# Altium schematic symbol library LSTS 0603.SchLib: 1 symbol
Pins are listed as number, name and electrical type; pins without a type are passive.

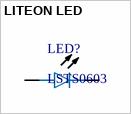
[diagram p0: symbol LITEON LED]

## LITEON LED
designator LED?, comment LSTS0603
LITE ON LED 0603
footprint LITEON_LED_0603
pins: 1 A, 2 K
